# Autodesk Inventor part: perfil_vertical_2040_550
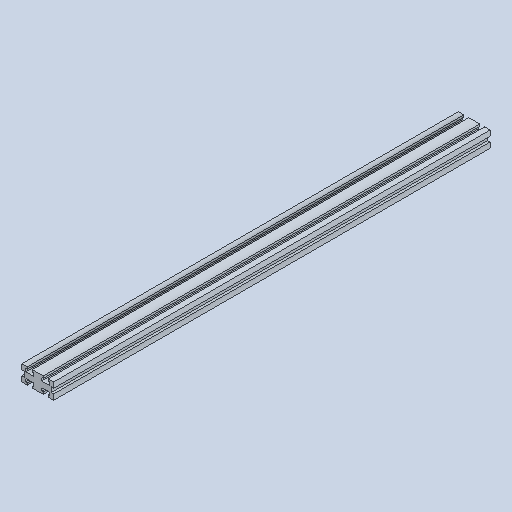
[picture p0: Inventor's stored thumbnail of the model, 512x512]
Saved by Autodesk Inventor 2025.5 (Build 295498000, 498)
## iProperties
Created: 2026-10
Part Number: perfil_vertical_2040_550
Material: Genérico
Document SubType Name: Modeling
Designer: Luis M
Density: 1 g/cm^3
Appearance: Valor por defecto
Author: Luis M
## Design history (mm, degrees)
feature "Base1"
node "Sólido1"
